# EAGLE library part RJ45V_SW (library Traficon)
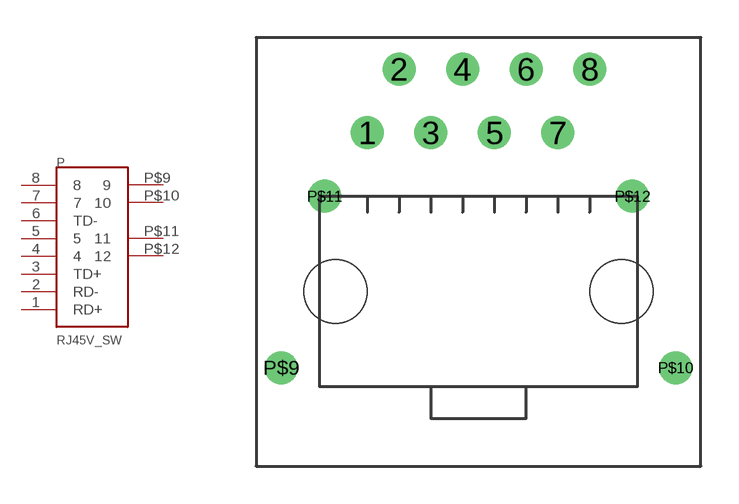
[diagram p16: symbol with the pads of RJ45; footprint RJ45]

Designator prefix P

## RJ45V_SW  [RJ45]
1  RD+  pas
2  RD-  pas
3  TD+  pas
4  4  pas
5  5  pas
6  TD-  pas
7  7  pas
8  8  pas
P$9  9  pas
P$10  10  pas
P$11  11  pas
P$12  12  pas

## Footprint RJ45 (pad centres in mm)
drill 0.813 round: 1 -4.445,6.35; 2 -3.175,8.89; 3 -1.905,6.35; 4 -0.635,8.89; 5 0.635,6.35; 6 1.905,8.89; 7 3.175,6.35; 8 4.445,8.89; P$9 -7.874,-3.048; P$10 7.874,-3.048; P$11 -6.147,3.81; P$12 6.147,3.81
hole 2.54 at -5.715,0
hole 2.54 at 5.715,0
